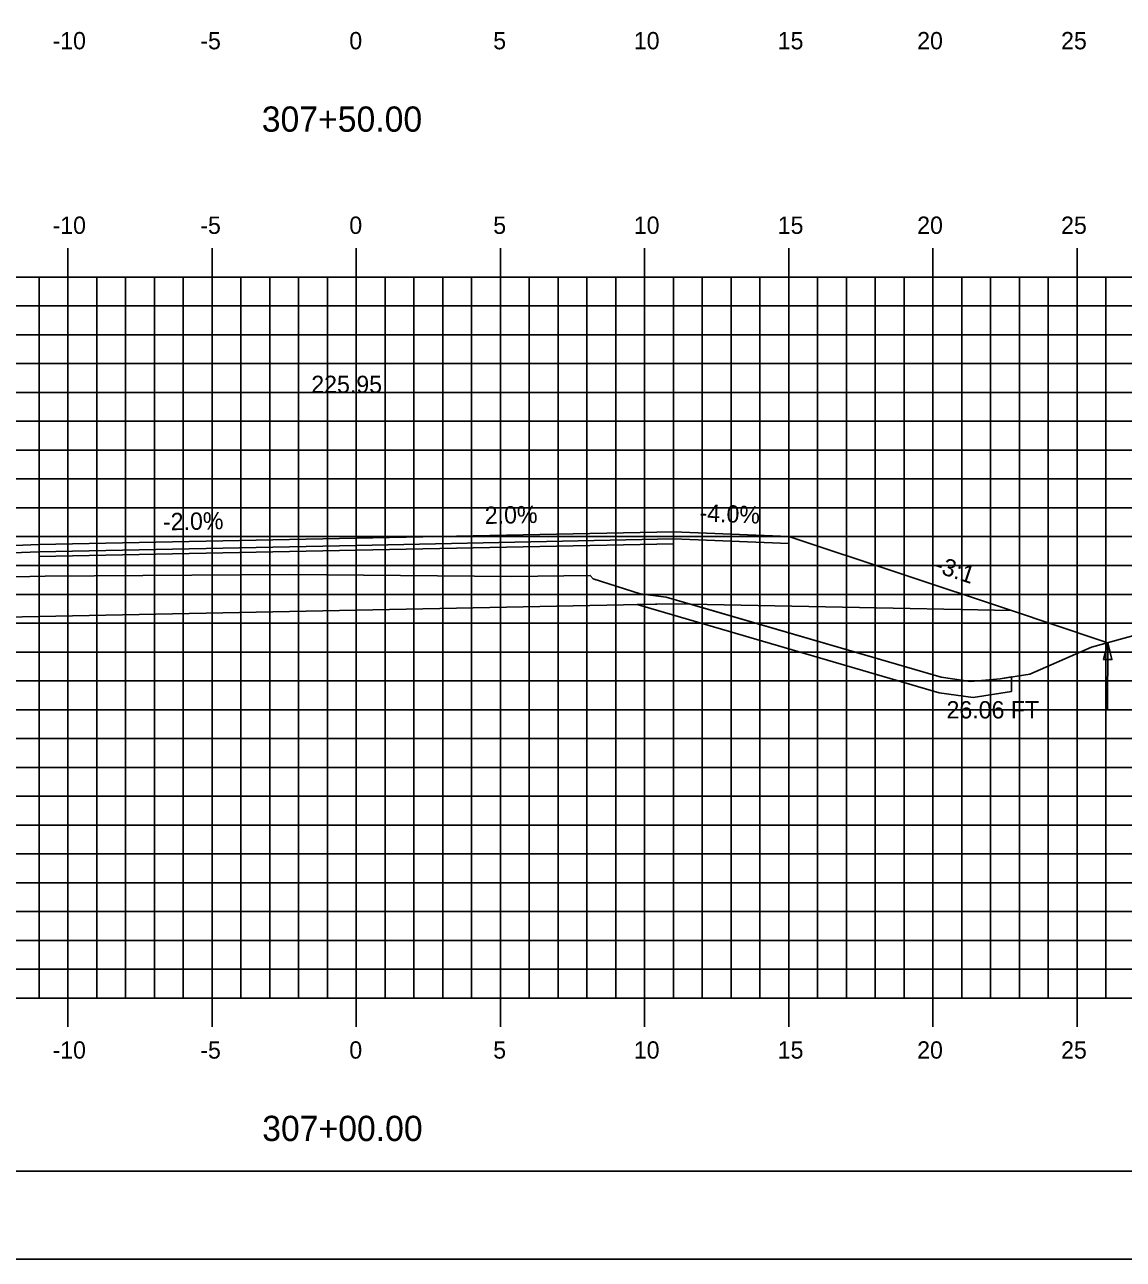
# Model space of a CAD drawing. Extents: x 1137654 to 1137824, y 608981 to 609091.
# Drawn here: x 1137725.91 to 1137764.01, y 608981.28 to 609024.09 of the extents above; entities that cross this region are included whole.
import ezdxf

# ---------------------------------------------------------------- set-up
doc = ezdxf.new("R2010")
doc.units = 0
for name, color, linetype in [('ANNOTATION', 7, 'Continuous'), ('BORDER', 7, 'Continuous'), ('D_Roadway_Centerline', 7, 'Continuous'), ('D_Roadway_Centerline_Text', 7, 'Continuous'), ('D_Roadway_Edge_Shoulder', 7, 'Continuous'), ('D_Roadway_Edge_TW', 7, 'Continuous'), ('D_Roadway_Pavement', 7, 'Continuous'), ('D_Roadway_SlopeLines', 7, 'Continuous'), ('D_Roadway_SubGrade', 7, 'Continuous'), ('D_Text_Standard', 7, 'Continuous'), ('H_V ANNOTATION', 7, 'Continuous'), ('MAJOR', 7, 'Continuous'), ('MINOR', 7, 'Continuous'), ('PLOT BOUNDARY', 7, 'Continuous'), ('S_Roadway_Centerline', 7, 'Continuous'), ('SHADING', 7, 'Continuous')]:
    doc.layers.add(name, color=color, linetype=linetype)

msp = doc.modelspace()

# ---------------------------------------------------------------- linework, layer by layer
msp.add_lwpolyline([(1137700.29, 608998.532), (1137711.685, 609002.33), (1137714.685, 609003.33), (1137722.408, 609005.904), (1137722.409, 609005.904), (1137726.409, 609006.064), (1137737.409, 609006.284), (1137748.409, 609006.504), (1137752.409, 609006.344), (1137760.133, 609003.77), (1137763.133, 609002.77), (1137763.471, 609002.657)])
at = {"layer": 'BORDER'}
msp.add_lwpolyline([(1137662.41, 608984.335), (1137822.41, 608984.335), (1137822.41, 609089.335), (1137662.41, 609089.335)], close=True, dxfattribs=at)
at = {"layer": 'D_Roadway_Edge_Shoulder'}
for points in [[(1137748.409, 609006.504), (1137752.409, 609006.344), (1137752.409, 609006.094), (1137748.409, 609006.254)], [(1137726.409, 609006.064), (1137722.409, 609005.904), (1137722.409, 609005.654), (1137726.409, 609005.814)]]:
    msp.add_lwpolyline(points, close=True, dxfattribs=at)
at = {"layer": 'D_Roadway_Edge_TW'}
msp.add_lwpolyline([(1137726.409, 609005.814), (1137726.409, 609006.064), (1137737.409, 609006.284), (1137748.409, 609006.504), (1137748.409, 609006.254), (1137737.409, 609006.034)], close=True, dxfattribs=at)
at = {"layer": 'D_Roadway_Pavement'}
msp.add_lwpolyline([(1137726.409, 609005.648), (1137726.409, 609005.814), (1137737.409, 609006.034), (1137748.409, 609006.254), (1137748.409, 609006.088), (1137737.409, 609005.868)], close=True, dxfattribs=at)
at = {"layer": 'D_Roadway_SlopeLines'}
for points in [[(1137760.133, 609001.469), (1137760.133, 609000.969), (1137758.803, 609000.762), (1137757.625, 609000.925), (1137747.148, 609003.979)], [(1137760.133, 609003.77), (1137763.133, 609002.77)]]:
    msp.add_lwpolyline(points, dxfattribs=at)
at = {"layer": 'D_Roadway_SubGrade'}
for points in [[(1137726.409, 609003.564), (1137726.409, 609005.648), (1137737.409, 609005.868), (1137748.409, 609006.088), (1137748.409, 609004.004), (1137737.409, 609003.784)], [(1137748.409, 609006.088), (1137748.409, 609006.254), (1137752.409, 609006.094), (1137752.409, 609006.344), (1137752.41, 609006.344), (1137760.133, 609003.77), (1137748.409, 609004.004)], [(1137726.409, 609005.648), (1137726.409, 609005.814), (1137722.409, 609005.654), (1137722.409, 609005.904), (1137722.408, 609005.904), (1137714.685, 609003.33), (1137726.409, 609003.564)]]:
    msp.add_lwpolyline(points, close=True, dxfattribs=at)
at = {"layer": 'D_Text_Standard'}
msp.add_lwpolyline([(1137763.471, 609002.657), (1137763.469, 609000.331), (1137762.789, 609000.331)], dxfattribs=at)
msp.add_lwpolyline([(1137763.471, 609002.657), (1137763.616, 609002.075), (1137763.325, 609002.075)], close=True, dxfattribs=at)
at = {"layer": 'MAJOR'}
for p, q in [((1137727.409, 609016.337), (1137727.409, 609015.335)), ((1137732.409, 609016.337), (1137732.409, 609015.335)), ((1137737.409, 609016.337), (1137737.409, 609015.335)), ((1137742.409, 609016.337), (1137742.409, 609015.335)), ((1137747.409, 609016.337), (1137747.409, 609015.335)), ((1137752.409, 609016.337), (1137752.409, 609015.335)), ((1137757.409, 609016.337), (1137757.409, 609015.335)), ((1137762.409, 609016.337), (1137762.409, 609015.335)), ((1137667.409, 609015.335), (1137807.409, 609015.335)), ((1137667.409, 609015.335), (1137807.409, 609015.335)), ((1137727.409, 608990.335), (1137727.409, 609015.335)), ((1137732.409, 608990.335), (1137732.409, 609015.335)), ((1137737.409, 608990.335), (1137737.409, 609015.335)), ((1137742.409, 608990.335), (1137742.409, 609015.335)), ((1137747.409, 608990.335), (1137747.409, 609015.335)), ((1137752.409, 608990.335), (1137752.409, 609015.335)), ((1137757.409, 608990.335), (1137757.409, 609015.335)), ((1137762.409, 608990.335), (1137762.409, 609015.335)), ((1137667.409, 609010.335), (1137807.409, 609010.335)), ((1137667.409, 609005.335), (1137807.409, 609005.335)), ((1137667.409, 609000.335), (1137807.409, 609000.335)), ((1137667.409, 608995.335), (1137807.409, 608995.335)), ((1137667.409, 608990.335), (1137807.409, 608990.335)), ((1137667.409, 608990.335), (1137807.409, 608990.335)), ((1137727.409, 608989.333), (1137727.409, 608990.335)), ((1137732.409, 608989.333), (1137732.409, 608990.335)), ((1137737.409, 608989.333), (1137737.409, 608990.335)), ((1137742.409, 608989.333), (1137742.409, 608990.335)), ((1137747.409, 608989.333), (1137747.409, 608990.335)), ((1137752.409, 608989.333), (1137752.409, 608990.335)), ((1137757.409, 608989.333), (1137757.409, 608990.335)), ((1137762.409, 608989.333), (1137762.409, 608990.335))]:
    msp.add_line(p, q, dxfattribs=at)
at = {"layer": 'MINOR'}
for p, q in [((1137726.409, 608990.335), (1137726.409, 609015.335)), ((1137728.409, 608990.335), (1137728.409, 609015.335)), ((1137729.409, 608990.335), (1137729.409, 609015.335)), ((1137730.409, 608990.335), (1137730.409, 609015.335)), ((1137731.409, 608990.335), (1137731.409, 609015.335)), ((1137733.409, 608990.335), (1137733.409, 609015.335)), ((1137734.409, 608990.335), (1137734.409, 609015.335)), ((1137735.409, 608990.335), (1137735.409, 609015.335)), ((1137736.409, 608990.335), (1137736.409, 609015.335)), ((1137738.409, 608990.335), (1137738.409, 609015.335)), ((1137739.409, 608990.335), (1137739.409, 609015.335)), ((1137740.409, 608990.335), (1137740.409, 609015.335)), ((1137741.409, 608990.335), (1137741.409, 609015.335)), ((1137743.409, 608990.335), (1137743.409, 609015.335)), ((1137744.409, 608990.335), (1137744.409, 609015.335)), ((1137745.409, 608990.335), (1137745.409, 609015.335)), ((1137746.409, 608990.335), (1137746.409, 609015.335)), ((1137748.409, 608990.335), (1137748.409, 609015.335)), ((1137749.409, 608990.335), (1137749.409, 609015.335)), ((1137750.409, 608990.335), (1137750.409, 609015.335)), ((1137751.409, 608990.335), (1137751.409, 609015.335)), ((1137753.409, 608990.335), (1137753.409, 609015.335)), ((1137754.409, 608990.335), (1137754.409, 609015.335)), ((1137755.409, 608990.335), (1137755.409, 609015.335)), ((1137756.409, 608990.335), (1137756.409, 609015.335)), ((1137758.409, 608990.335), (1137758.409, 609015.335)), ((1137759.409, 608990.335), (1137759.409, 609015.335)), ((1137760.409, 608990.335), (1137760.409, 609015.335)), ((1137761.409, 608990.335), (1137761.409, 609015.335)), ((1137763.409, 608990.335), (1137763.409, 609015.335)), ((1137667.409, 609014.335), (1137807.409, 609014.335)), ((1137667.409, 609013.335), (1137807.409, 609013.335)), ((1137667.409, 609012.335), (1137807.409, 609012.335)), ((1137667.409, 609011.335), (1137807.409, 609011.335)), ((1137667.409, 609009.335), (1137807.409, 609009.335)), ((1137667.409, 609008.335), (1137807.409, 609008.335)), ((1137667.409, 609007.335), (1137807.409, 609007.335)), ((1137667.409, 609006.335), (1137807.409, 609006.335)), ((1137667.409, 609004.335), (1137807.409, 609004.335)), ((1137667.409, 609003.335), (1137807.409, 609003.335)), ((1137667.409, 609002.335), (1137807.409, 609002.335)), ((1137667.409, 609001.335), (1137807.409, 609001.335)), ((1137667.409, 608999.335), (1137807.409, 608999.335)), ((1137667.409, 608998.335), (1137807.409, 608998.335)), ((1137667.409, 608997.335), (1137807.409, 608997.335)), ((1137667.409, 608996.335), (1137807.409, 608996.335)), ((1137667.409, 608994.335), (1137807.409, 608994.335)), ((1137667.409, 608993.335), (1137807.409, 608993.335)), ((1137667.409, 608992.335), (1137807.409, 608992.335)), ((1137667.409, 608991.335), (1137807.409, 608991.335))]:
    msp.add_line(p, q, dxfattribs=at)
at = {"layer": 'PLOT BOUNDARY'}
msp.add_lwpolyline([(1137654.316, 608981.276), (1137824.316, 608981.276), (1137824.316, 609091.276), (1137654.316, 609091.276)], close=True, dxfattribs=at)
at = {"layer": 'S_Roadway_Centerline'}
msp.add_lwpolyline([(1137667.409, 608999.427), (1137671.375, 608999.533), (1137682.176, 608998.539), (1137682.929, 608998.559), (1137705.808, 608998.523), (1137708.965, 608998.916), (1137713.914, 609000.539), (1137720.407, 609004.41), (1137723.296, 609004.805), (1137723.932, 609004.904), (1137726.625, 609004.961), (1137735.098, 609005.026), (1137742.791, 609004.952), (1137745.524, 609004.989), (1137745.621, 609004.875), (1137747.251, 609004.35), (1137748.161, 609004.238), (1137757.699, 609001.458), (1137758.717, 609001.317), (1137759.74, 609001.407), (1137760.775, 609001.568), (1137762.91, 609002.502), (1137768.911, 609004.157)], dxfattribs=at)
at = {"layer": 'SHADING'}
for p, q in [((1137748.409, 609004.004), (1137747.148, 609003.979)), ((1137749.004, 609003.992), (1137748.409, 609004.004))]:
    msp.add_line(p, q, dxfattribs=at)
for points in [[(1137747.148, 609003.979), (1137757.625, 609000.925), (1137758.803, 609000.762), (1137760.133, 609000.969), (1137760.133, 609001.469)], [(1137760.133, 609001.469), (1137759.74, 609001.407), (1137758.717, 609001.317), (1137757.699, 609001.458), (1137749.004, 609003.992)]]:
    msp.add_lwpolyline(points, dxfattribs=at)

# ---------------------------------------------------------------- texts
at = {"layer": 'ANNOTATION'}
for s, rotation, p in [('2.0%', 1.1458, (1137741.873, 609006.774)), ('-4.0%', 357.7094, (1137749.305, 609006.869)), ('-2.0%', 1.1458, (1137730.712, 609006.551)), ('-3:1', 341.5652, (1137757.421, 609005.128))]:
    msp.add_text(s, height=0.6, rotation=rotation, dxfattribs=at).set_placement(p)
at = {"layer": 'D_Roadway_Centerline'}
for s, p in [('C', (1137737.404, 609006.284)), ('L', (1137737.409, 609006.277))]:
    msp.add_text(s, height=0.0146, dxfattribs=at).set_placement(p)
at = {"layer": 'D_Roadway_Centerline_Text'}
msp.add_text('225.95', height=0.6, dxfattribs=at).set_placement((1137735.849, 609011.316))
at = {"layer": 'D_Text_Standard'}
msp.add_text('26.06 FT', height=0.6, dxfattribs=at).set_placement((1137757.881, 609000.031))
at = {"layer": 'H_V ANNOTATION'}
for s, height, p in [('-10', 0.6, (1137726.874, 609023.235)), ('-5', 0.6, (1137732, 609023.235)), ('0', 0.6, (1137737.168, 609023.235)), ('5', 0.6, (1137742.16, 609023.235)), ('10', 0.6, (1137747.035, 609023.235)), ('15', 0.6, (1137752.027, 609023.235)), ('20', 0.6, (1137756.863, 609023.235)), ('25', 0.6, (1137761.855, 609023.235)), ('307+50.00', 0.875, (1137734.132, 609020.378)), ('-10', 0.6, (1137726.874, 609016.835)), ('-5', 0.6, (1137732, 609016.835)), ('0', 0.6, (1137737.168, 609016.835)), ('5', 0.6, (1137742.16, 609016.835)), ('10', 0.6, (1137747.035, 609016.835)), ('15', 0.6, (1137752.027, 609016.835)), ('20', 0.6, (1137756.863, 609016.835)), ('25', 0.6, (1137761.855, 609016.835)), ('-10', 0.6, (1137726.874, 608988.235)), ('-5', 0.6, (1137732, 608988.235)), ('0', 0.6, (1137737.168, 608988.235)), ('5', 0.6, (1137742.16, 608988.235)), ('10', 0.6, (1137747.035, 608988.235)), ('15', 0.6, (1137752.027, 608988.235)), ('20', 0.6, (1137756.863, 608988.235)), ('25', 0.6, (1137761.855, 608988.235)), ('307+00.00', 0.875, (1137734.148, 608985.378))]:
    msp.add_text(s, height=height, dxfattribs=at).set_placement(p)
at = {"layer": 'S_Roadway_Centerline'}
for s, p in [('L', (1137735.09, 609005.019)), ('C', (1137735.093, 609005.026))]:
    msp.add_text(s, height=0.0146, dxfattribs=at).set_placement(p)

doc.saveas('drawing.dxf')
